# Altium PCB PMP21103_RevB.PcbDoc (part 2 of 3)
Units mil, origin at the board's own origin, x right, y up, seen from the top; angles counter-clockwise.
Board outline 3500 x 4000 mil, 4 copper layers (Top Layer, Signal Layer 1, Signal Layer 2, Bottom Layer), stack 61.2 mil thick; 194 components, 123 nets, 630 pads, 189 vias.
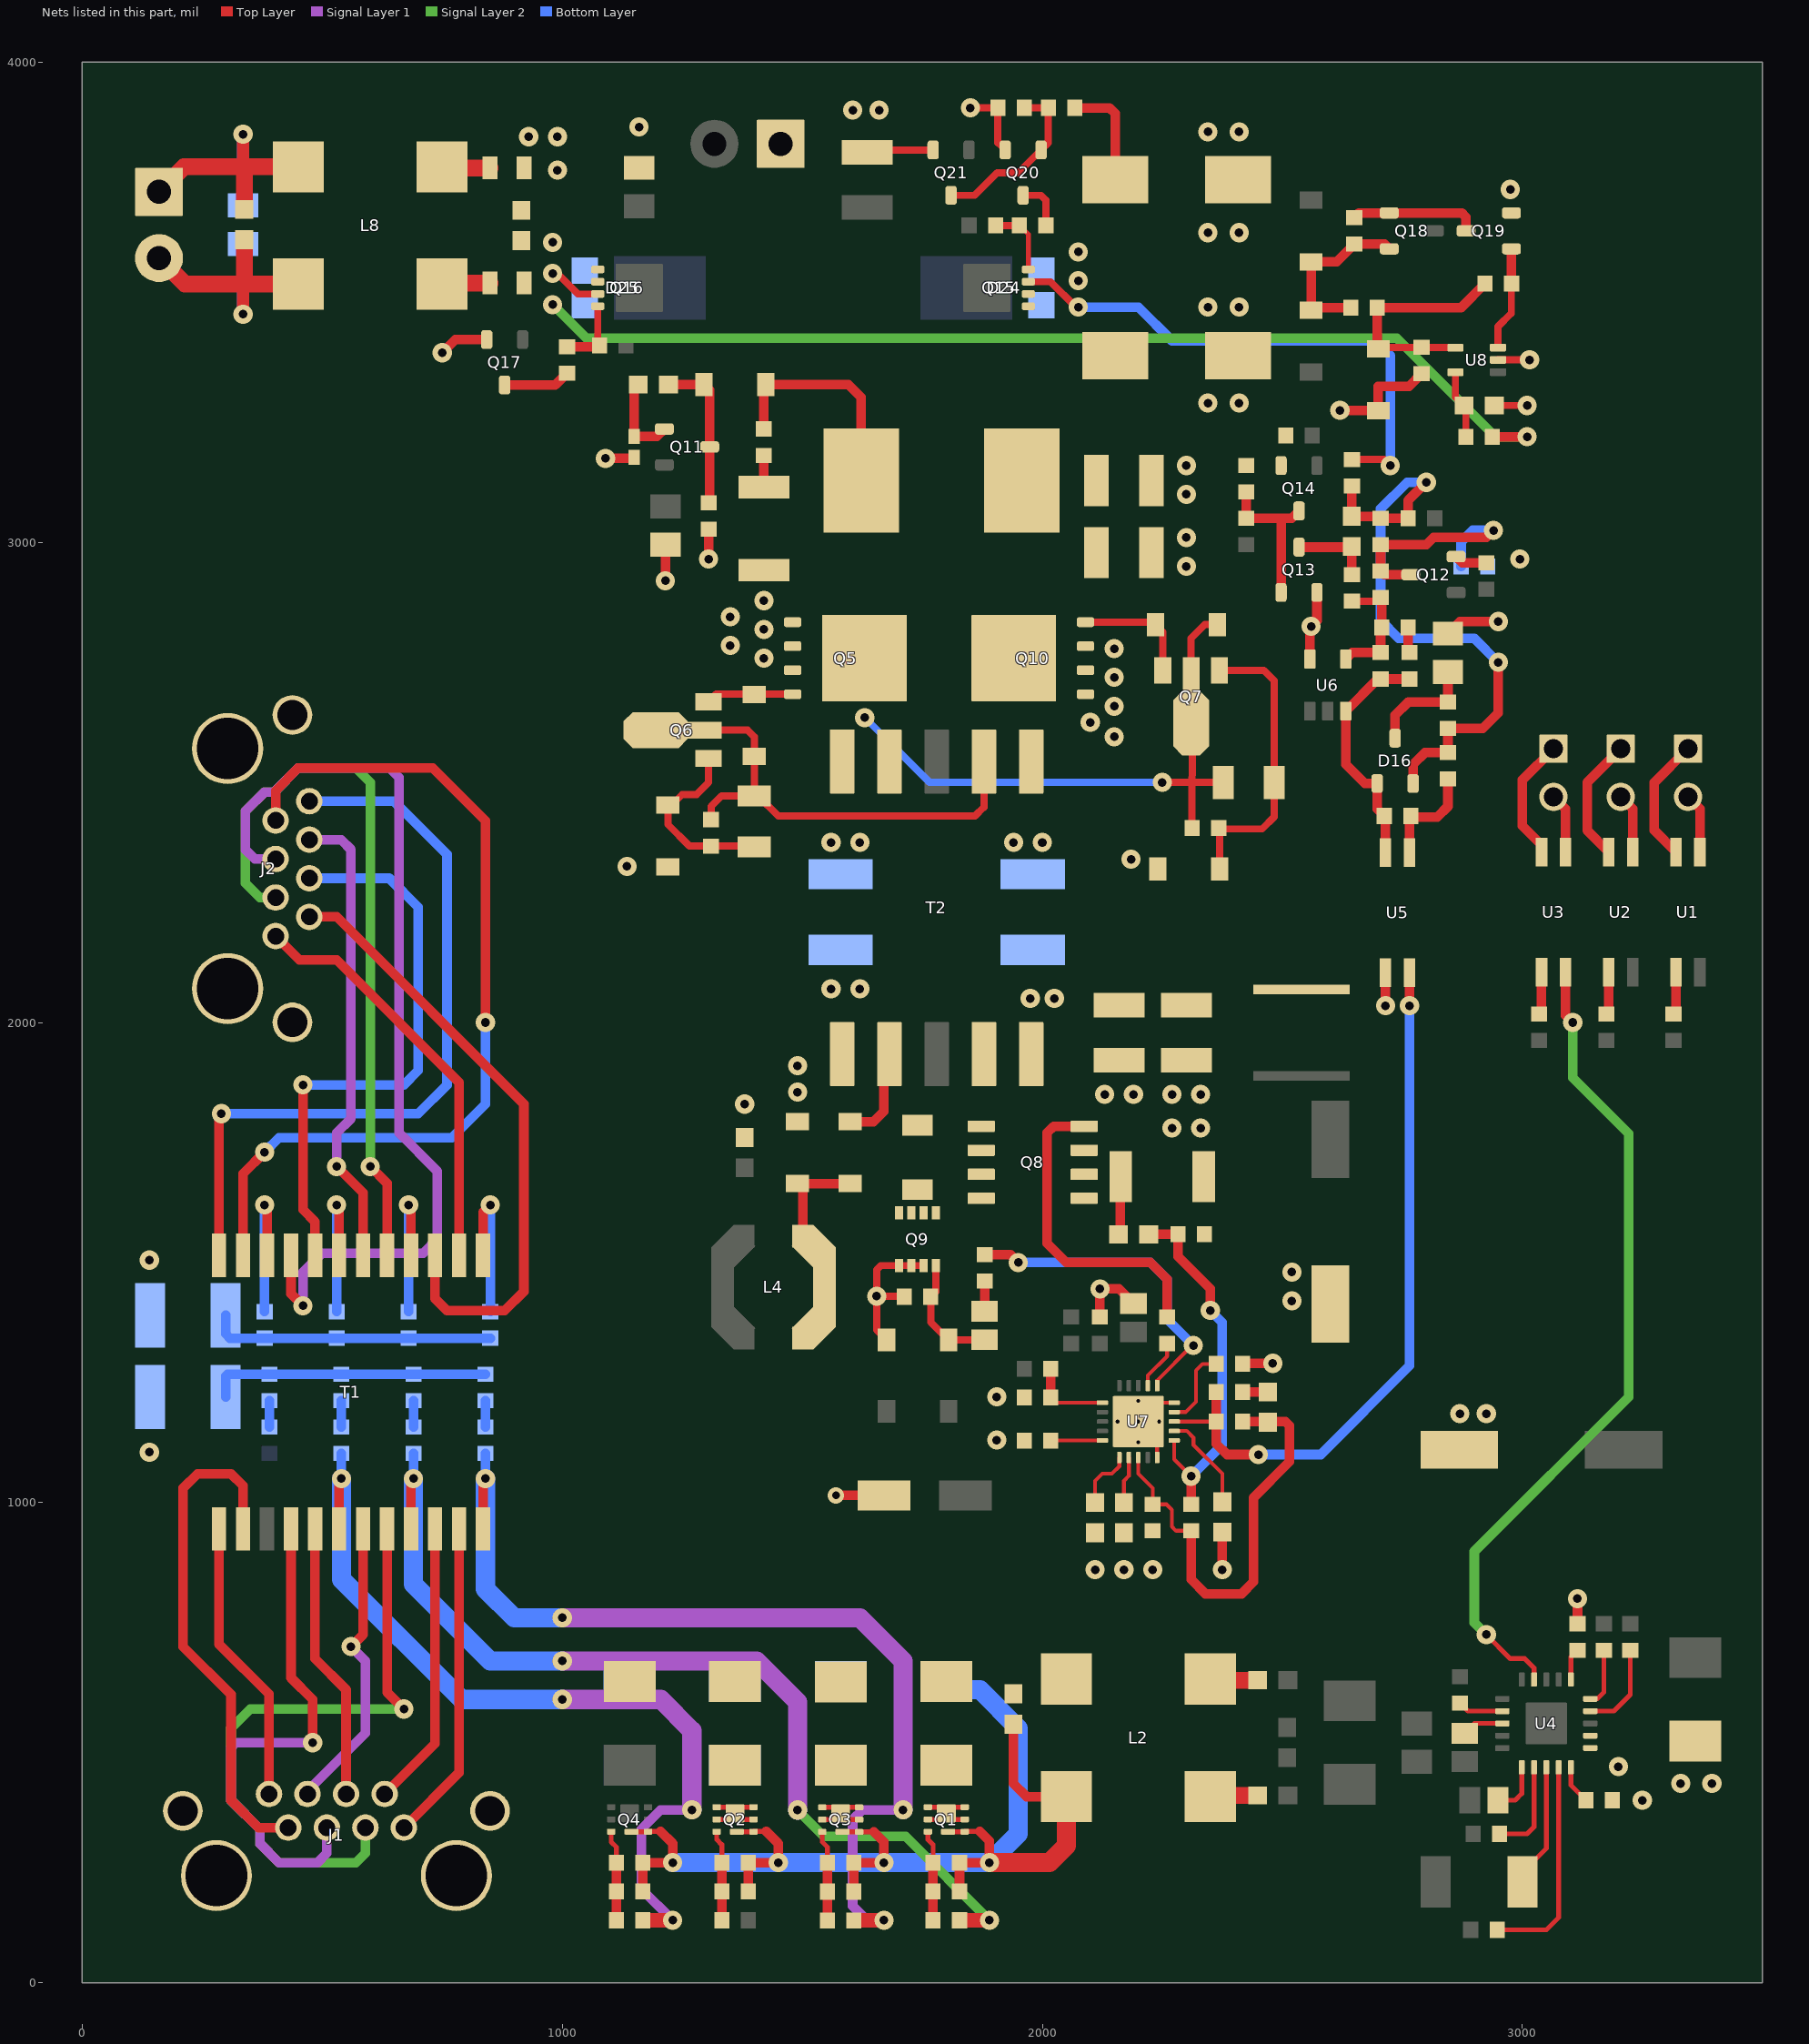
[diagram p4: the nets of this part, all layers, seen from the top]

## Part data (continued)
D10 D12: "Diode, Zener, 10 V, 500 mW, SOD-123", Manufacturer="Diodes Inc.", Power_W=0.5, Supplier Part Number 1=MMSZ5240B-FDICT-ND, Value1=0.5W
D15: "Diode, Zener, 9.1 V, 300 mW, SOD-523", Manufacturer="Diodes Inc.", Power_W=0.3, Supplier Part Number 1=BZT52C9V1TDICT-ND, Value1=0.3W
D16: "Diode, Schottky, 30 V, 0.2 A, SOT-23", Manufacturer="Diodes Inc.", Supplier Part Number 1=BAT54S-FDICT-ND, Value1=0.2A, Value2=0.65V
D18: "Diode, Zener, 5.1 V, 500 mW, SOD-123", Manufacturer="Diodes Inc.", Power_W=0.5, Supplier Part Number 1=MMSZ5231B-FDICT-ND, Value1=0.5W
D20 D21 D22 D23: library part CMP-0028397-2, "Diode, Schottky, 100 V, 2 A, SMB", Manufacturer="Diodes Inc.", Value1=2A, Value2=0.79V
D24 D25: library part CMP-0076913-1, "Diode, Schottky, 35 V, 8 A, PowerDI5", Manufacturer="Diodes Inc.", Supplier Part Number 1=PDS835LDICT-ND, Value1=8A, Value2=0.46V
D26: library part CMP-0029032-2, "Diode, Switching, 100 V, 0.2 A, SOD-123", Manufacturer="ON Semiconductor", Value1=0.2A, Value2=1V
J1 J2: "RJ-45, Right Angle, No LED, tab up", Manufacturer=AMP, Supplier Part Number 1=A97716-ND
J3 J4 J5: "Header, 100mil, 2x1, Tin, TH", Manufacturer="Sullins Connector Solutions", Supplier Part Number 1=S1012E-02-ND
J6 J7: library part CMP-0074913-1, "Terminal Block, 3.5mm Pitch, 2x1, TH", Color=Grey, Current_A=6A, Manufacturer="On-Shore Technology", Supplier Part Number 1=ED1514-ND, Voltage_V=150V
L1 L3: "Ferrite Bead, 220 ohm @ 100 MHz, 2.2 A, 0603", Manufacturer=TDK, Supplier Part Number 1=445-1565-1-ND, Value1="0.05 ohm", Value2=2.2A
L2: "Coupled inductor, 250 µH,  A, 0.035 ohm, SMD", Manufacturer="Wurth Elektronik", Supplier Part Number 1=732-1491-1-ND, ValueDisplayed=250µH
L4: "Inductor, Shielded Drum Core, Ferrite, 1.5 mH, 0.14 A, 4.6 ohm, SMD", Manufacturer=Coilcraft, Value1="4.6 ohm", Value2=0.14A, ValueDisplayed=1.5mH
L5: "Inductor, Shielded Drum Core, Ferrite, 3.3 µH, 1.73 A, 0.03 ohm, SMD", Manufacturer=Coilcraft, Value1="0.03 ohm", Value2=1.73A, ValueDisplayed=3.3µH
L6: "Inductor, Shielded Drum Core, Ferrite, 22 µH, 4 A, 0.04 ohm, SMD", Manufacturer=Coilcraft, Value1="0.04 ohm", Value2=4A, ValueDisplayed=22µH
L7 L9: library part CMP-0003428-2, "Ferrite Bead, 30 ohm @ 100 MHz, 6 A, 0805", Manufacturer=TDK, Supplier Part Number 1=445-1566-1-ND, Value1="0.01 ohm", Value2=6A, ValueDisplayed="30 ohm"
L8: library part CMP-0078807-1, "Coupled inductor, 9 µH, 0.011 ohm, SMD", Manufacturer="Wurth Elektronik", Supplier Part Number 1=732-2215-1-ND, ValueDisplayed=9µH
Q1 Q2 Q3 Q4: "MOSFET, N-CH, 100 V, 4.5 A, DQK0006C (WSON-6)", Alternate Manufacturer=None, Manufacturer="Texas Instruments", Value1="? ohm", Value2="? nC"
Q5 Q10: "MOSFET, N-CH, 60 V, 50 A, DQJ0008A (VSONP-8)", Alternate Manufacturer=None, Manufacturer="Texas Instruments", Supplier Part Number 1=296-35583-1-ND, Value1="0.0098 ohm", Value2="22 nC"
Q6 Q7: library part "FCX493TA, Diodes Inc.", "Transistor, NPN, 100 V, 1 A, SOT-89", Manufacturer="Diodes Inc.", Supplier Part Number 1=FCX493CT-ND, Value1="1 A", Value2=300
Q8: "MOSFET, N-CH, 150 V, 4.1 A, SOIC-8", Alternate Manufacturer=None, Manufacturer="Fairchild Semiconductor", Supplier Part Number 1=FDS86242CT-ND, Value1="? ohm", Value2="8.9 nC"
Q9: "MOSFET, P-CH, -150 V, -3 A, QFN-8", Alternate Manufacturer=None, Manufacturer="Fairchild Semiconductor", Supplier Part Number 1=FDMC2523PCT-ND, Value1="? ohm", Value2="6.2 nC"
Q11: library part "MMBT3904-7-F, Diodes Inc.", "Transistor, NPN, 40 V, 0.2 A, SOT-23", Manufacturer="Diodes Inc.", Supplier Part Number 1=MMBT3904-FDICT-ND, Value1="0.2 A", Value2=400
Q12 Q13 Q14 Q17 Q20 Q21: "MOSFET, N-CH, 60 V, 0.36 A, SOT-23", Alternate Manufacturer=None, Manufacturer=Nexperia, Supplier Part Number 1=568-5818-1-ND, Value1="2 ohm", Value2="0.6 nC"
Q15 Q16: library part CMP-0000025-2, "MOSFET, P-CH, -20 V, -15 A, DNH0008A (VSONP-8)", Alternate Manufacturer=None, Manufacturer="Texas Instruments", Supplier Part Number 1=CSD25402Q3A-ND, Value1=0.007, Value2="7.5 nC"
Q18: "MOSFET, P-CH, -60 V, -0.3 A, SOT-23", Alternate Manufacturer=None, Manufacturer=Nexperia, Supplier Part Number 1=568-6217-1-ND, Value1="2.7 ohm", Value2="3 nC"
Q19: "MOSFET, N-CH, 100 V, 0.17 A, SOT-23", Alternate Manufacturer=None, Manufacturer="Fairchild Semiconductor", Supplier Part Number 1=BSS123NCT-ND, Value1="10 ohm", Value2="1.8 nC"
R1 R4 R6 R37 R48 R49 R55 R65: "RES, 10.0 k, 1%, 0.1 W, 0603", Manufacturer=Vishay-Dale, Power_W=0.1, Supplier Part Number 1=541-10.0KHCT-ND, TempCo="100 ppm/C", Tolerance_%=1, Value1=1%, Value2=0.1W, Value_Code=10k0, ValueDisplayed=10.0k
R2 R3 R5 R7 R8 R9 R10 R11: "RES, 75.0 ohm, 1%, 0.1W, 0603", Manufacturer=Vishay-Dale, Power_W=0.1, Supplier Part Number 1=541-75.0HCT-ND, TempCo="100 ppm/C", Tolerance_%=1, Value1=1%, Value2=0.1W, Value_Code=75R0
R12: "RES, 27.4 k, 1%, 0.1 W, 0603", Manufacturer=Vishay-Dale, Power_W=0.1, Supplier Part Number 1=541-27.4KHCT-ND, TempCo="100 ppm/C", Tolerance_%=1, Value1=1%, Value2=0.1W, Value_Code=27k4, ValueDisplayed=27.4k
R13 R14 R24 R25 R38 R42 R43 R61 R72: "RES, 0, 5%, 0.1 W, 0603", Manufacturer=Vishay-Dale, Power_W=0.1, Supplier Part Number 1=541-0.0GCT-ND, TempCo="200 ppm/C", Tolerance_%=5, Value1=5%, Value2=0.1W, Value_Code=0000, ValueDisplayed=0
R15 R16 R17 R18: "RES, 1.00 M, 1%, 0.1 W, 0603", Manufacturer=Vishay-Dale, Power_W=0.1, Supplier Part Number 1=541-1.00MHCT-ND, TempCo="100 ppm/C", Tolerance_%=1, Value1=1%, Value2=0.1W, Value_Code=1M00, ValueDisplayed=1.00M
R19: "RES, 53.6 k, 1%, 0.1 W, 0603", Manufacturer=Vishay-Dale, Power_W=0.1, Supplier Part Number 1=541-53.6KHCT-ND, TempCo="100 ppm/C", Tolerance_%=1, Value1=1%, Value2=0.1W, Value_Code=53k6, ValueDisplayed=53.6k
R20 R21 R22 R23: "RES, 232 k, 1%, 0.1 W, 0603", Manufacturer=Vishay-Dale, Power_W=0.1, Supplier Part Number 1=541-232KHCT-ND, TempCo="100 ppm/C", Tolerance_%=1, Value1=1%, Value2=0.1W, Value_Code=232k
R26: "RES, 63.4, 1%, 0.125 W, 0805", Manufacturer=Vishay-Dale, Power_W=0.125, Supplier Part Number 1=541-63.4CCT-ND, TempCo="100 ppm/C", Tolerance_%=1, Value1=1%, Value2=0.125W, Value_Code=63R4, ValueDisplayed=63.4
R27: "RES, 1.21 k, 1%, 0.125 W, 0805", Manufacturer=Vishay-Dale, Power_W=0.125, Supplier Part Number 1=541-1.21KCCT-ND, TempCo="100 ppm/C", Tolerance_%=1, Value1=1%, Value2=0.125W, Value_Code=1k21, ValueDisplayed=1.21k
R28: library part CMP-0016077-3, "RES, 1.3 k, 5%, 0.75 W, AEC-Q200 Grade 0, 2010", Manufacturer=Vishay-Dale, Power_W=750mW, Supplier Part Number 1=541-1.3KWCT-ND, TempCo="200 ppm/C", Tolerance_%=5%, Value2=0.75W, Value_Code=1k30, ValueDisplayed=1.3k
R29: "RES, 49.9 k, 1%, 0.1 W, 0603", Manufacturer=Vishay-Dale, Power_W=0.1, Supplier Part Number 1=541-49.9KHCT-ND, TempCo="100 ppm/C", Tolerance_%=1, Value1=1%, Value2=0.1W, Value_Code=49k9, ValueDisplayed=49.9k
R30 R31: "RES, 2.0 k, 5%, 0.25 W, 1206", Manufacturer=Vishay-Dale, Power_W=0.25, Supplier Part Number 1=541-2.0KECT-ND, TempCo="200 ppm/C", Tolerance_%=5, Value1=5%, Value2=0.25W, Value_Code=2k00, ValueDisplayed=2.0k
R32: "RES, 10, 5%, 0.75 W, AEC-Q200 Grade 0, 2010", Manufacturer=Vishay-Dale, Power_W=0.75, Supplier Part Number 1=541-10.0WCT-ND, TempCo="200 ppm/C", Tolerance_%=5, Value1=5%, Value2=0.75W, Value_Code=10R0, ValueDisplayed=10
R33 R41: "RES, 4.7, 5%, 0.1 W, 0603", Manufacturer=Vishay-Dale, Power_W=0.1, Supplier Part Number 1=541-4.7GCT-ND, TempCo="200 ppm/C", Tolerance_%=5, Value1=5%, Value2=0.1W, Value_Code=4R70, ValueDisplayed=4.7
R34 R35: "RES, 121 k, 1%, 0.1 W, 0603", Manufacturer=Vishay-Dale, Power_W=0.1, Supplier Part Number 1=541-121KHCT-ND, TempCo="100 ppm/C", Tolerance_%=1, Value1=1%, Value2=0.1W, Value_Code=121k
R36 R60 R73: "RES, 1.00 k, 1%, 0.1 W, 0603", Manufacturer=Vishay-Dale, Power_W=0.1, Supplier Part Number 1=541-1.00KHCT-ND, TempCo="100 ppm/C", Tolerance_%=1, Value1=1%, Value2=0.1W, Value_Code=1k00, ValueDisplayed=1.00k
R39: "RES, 4.22 k, 1%, 0.1 W, 0603", Manufacturer=Vishay-Dale, Power_W=0.1, Supplier Part Number 1=541-4.22KHCT-ND, TempCo="100 ppm/C", Tolerance_%=1, Value1=1%, Value2=0.1W, Value_Code=4k22, ValueDisplayed=4.22k
R40: "RES, 0.1 ohm, 1%, 0.5W, 2010", Manufacturer=Panasonic, Power_W=0.5, TempCo="100 ppm/C", Tolerance_%=1, Value1=1%, Value2=0.5W, Value_Code=R100
R44: "RES, 15.0 k, 1%, 0.1 W, 0603", Manufacturer=Vishay-Dale, Power_W=0.1, Supplier Part Number 1=541-15.0KHCT-ND, TempCo="100 ppm/C", Tolerance_%=1, Value1=1%, Value2=0.1W, Value_Code=15k0, ValueDisplayed=15.0k
R45: "RES, 21.5 k, 1%, 0.1 W, 0603", Manufacturer=Vishay-Dale, Power_W=0.1, Supplier Part Number 1=541-21.5KHCT-ND, TempCo="100 ppm/C", Tolerance_%=1, Value1=1%, Value2=0.1W, Value_Code=21k5, ValueDisplayed=21.5k
R46: "RES, 28.7 k, 1%, 0.1 W, 0603", Manufacturer=Vishay-Dale, Power_W=0.1, Supplier Part Number 1=541-28.7KHCT-ND, TempCo="100 ppm/C", Tolerance_%=1, Value1=1%, Value2=0.1W, Value_Code=28k7, ValueDisplayed=28.7k
R47 R51 R52 R57 R63 R64 R66 R70 R71 R75 R76: "RES, 4.99 k, 1%, 0.1 W, 0603", Manufacturer=Vishay-Dale, Power_W=0.1, Supplier Part Number 1=541-4.99KHCT-ND, TempCo="100 ppm/C", Tolerance_%=1, Value1=1%, Value2=0.1W, Value_Code=4k99, ValueDisplayed=4.99k
R50: "RES, 5.90 k, 1%, 0.1 W, 0603", Manufacturer=Vishay-Dale, Power_W=0.1, Supplier Part Number 1=541-5.90KHCT-ND, TempCo="100 ppm/C", Tolerance_%=1, Value1=1%, Value2=0.1W, Value_Code=5k90, ValueDisplayed=5.90k
R53: "RES, 80.6 k, 1%, 0.1 W, 0603", Manufacturer=Vishay-Dale, Power_W=0.1, Supplier Part Number 1=541-80.6KHCT-ND, TempCo="100 ppm/C", Tolerance_%=1, Value1=1%, Value2=0.1W, Value_Code=80k6, ValueDisplayed=80.6k
R54 R62: "RES, 2.00 k, 1%, 0.1 W, 0603", Manufacturer=Vishay-Dale, Power_W=0.1, Supplier Part Number 1=541-2.00KHCT-ND, TempCo="100 ppm/C", Tolerance_%=1, Value1=1%, Value2=0.1W, Value_Code=2k00, ValueDisplayed=2.00k
R56: "RES, 64.9 k, 1%, 0.1 W, 0603", Manufacturer=Vishay-Dale, Power_W=0.1, Supplier Part Number 1=541-64.9KHCT-ND, TempCo="100 ppm/C", Tolerance_%=1, Value1=1%, Value2=0.1W, Value_Code=64k9, ValueDisplayed=64.9k
R58: library part CMP-0021990-2, "RES, 100 k, 1%, 0.1 W, 0603", Manufacturer=Vishay-Dale, Power_W=100mW, Supplier Part Number 1=541-100KHCT-ND, TempCo="100 ppm/C", Tolerance_%=1%, Value2=0.1W, Value_Code=100k
R59 R68: "RES, 100 k, 1%, 0.1 W, 0603", Manufacturer=Vishay-Dale, Power_W=0.1, Supplier Part Number 1=541-100KHCT-ND, TempCo="100 ppm/C", Tolerance_%=1, Value1=1%, Value2=0.1W, Value_Code=100k
R67: "RES, 20.0 k, 1%, 0.1 W, 0603", Manufacturer=Vishay-Dale, Power_W=0.1, Supplier Part Number 1=541-20.0KHCT-ND, TempCo="100 ppm/C", Tolerance_%=1, Value1=1%, Value2=0.1W, Value_Code=20k0, ValueDisplayed=20.0k
R69: "RES, 12.7 k, 1%, 0.1 W, 0603", Manufacturer=Vishay-Dale, Power_W=0.1, Supplier Part Number 1=541-12.7KHCT-ND, TempCo="100 ppm/C", Tolerance_%=1, Value1=1%, Value2=0.1W, Value_Code=12k7, ValueDisplayed=12.7k
R74: library part CMP-0021116-2, "RES, 2.49 k, 1%, 0.125 W, 0805", Manufacturer=Vishay-Dale, Power_W=125mW, Supplier Part Number 1=541-2.49KCCT-ND, TempCo="100 ppm/C", Tolerance_%=1%, Value2=0.125W, Value_Code=2k49, ValueDisplayed=2.49k
T1: "Transformer, 350 uH, SMT", Manufacturer="Wurth Elektronik", ValueDisplayed=350µH
T2: library part CMP-0077243-1, "Transformer, 100.5 uH, SMT", Manufacturer=Mentech, ValueDisplayed=100.5µH
U1 U2 U3 U5: "Optocoupler, 3.75 kV, 80-160% CTR, SMT", Manufacturer="Fairchild Semiconductor", Supplier Part Number 1=HMHA2801A-ND, Voltage_Isolation_Vrms=3750V
U4: "High-Power PoE PD Interface with Advanced Startup, RGW0020B (VQFN-20)", Alternate Manufacturer="Texas Instruments", Alternate PartNumber=TPS2373-4RGWT
U6: "Adjustable Precision Shunt Regulator, DBV0005A (SOT-23-5)", Alternate Manufacturer="Texas Instruments", Alternate PartNumber=TL431AIDBVT
U7: library part CMP-0031996-2, "Advanced Active Clamp PWM Controller with Current Control, -40 to +125 degC, 20-pin QFN (RGP), Green (RoHS & no Sb/Br)", Frequency(Max)(kHz)=1000, Manufacturer="Texas Instruments", Rating=Catalog
U8: library part CMP-0032337-1, "Single Voltage Detector, 1 Supply Monitored, -40 to 85 degC, 5-pin SC70 (DCK), Green (RoHS & no Sb/Br)", Manufacturer="Texas Instruments", Rating=Catalog, Threshold Voltage 1 (typ)(Typ)(V)=Adjustable

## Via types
v1: diameter 40, hole 18, Top Layer to Bottom Layer, 163 vias
v2: diameter 30, hole 12, Top Layer to Bottom Layer, 12 vias
v3: diameter 19.68, hole 7.87, Top Layer to Bottom Layer, 10 vias
v4: diameter 34, hole 16, Top Layer to Bottom Layer, 4 vias

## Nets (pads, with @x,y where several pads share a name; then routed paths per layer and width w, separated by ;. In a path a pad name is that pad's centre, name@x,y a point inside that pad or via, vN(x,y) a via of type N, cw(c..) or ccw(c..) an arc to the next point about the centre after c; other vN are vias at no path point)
12V_AUX: C43.1 D25.1 D25.2 L7.1 Q16.1 Q16.2 Q16.3 R68.1 | length 2318.1
  Top Layer w15: v1@990,3560 1032.8,3517.2 Q16.3@1073.98,3517.2
  Top Layer w20: R68.1@2937.56,3220 v1(3010,3220)
  Signal Layer 2 w20: v1(980,3495) 1050,3425 2738.74,3425 2943.74,3220 v1(3010,3220)
  other v1: 980,3560 980,3625
12V_POE: C18.1 C22.1 C23.1 C37.1 D24.1 D24.2 L6.2 Q15.1 Q15.2 Q15.3 R42.2 R75.2 | length 1354.2
  Top Layer w15: Q15.3@1971.02,3542.8 2017.2,3542.8 v1@2070,3490 ; R42.2@2645,3172.56 2712.44,3172.56 v1(2725,3160)
  Top Layer w20: R75.2@2067.56,3905 2140,3905 2152.05,3892.95 C37.1@2152.05,3755
  Bottom Layer w20: v1(2075,3490) 2200,3490 2270,3420 2693.74,3420 2725,3388.74 v1(2725,3160)
  other v1: 2075,3545 2075,3605
BSVG: C1.1 C6.2 J1.9 J1.10 J1.11 J1.12 J2.9 J2.10 J2.11 J2.12
  other v1: 140,1105 140,1505
BT: U3.2 U4.19 | length 1730.4
  Top Layer w10: v1(2925,725) 2975,675 3005,675 3024.41,655.59 U4.19@3024.41,631.54
  Top Layer w20: U3.2@3090,2105 3090,2015 v1(3105,2000)
  Signal Layer 2 w20: v1(2925,725) 2900,750 2900,898.31 3221.69,1220 3221.69,1768.31 3105,1885 v1(3105,2000)
GND: C16.1 C18.2 C22.2 C23.2 C29.1 C30.1 C31.2 C36.2 C37.2 C40.2 C41.2 C43.2 C44.1 D10.2 D12.2 D15.2 D18.2 J3.2 J4.2 J5.2 J6.1 L9.1 Q5.1 Q5.2 Q5.3 Q10.1 Q10.2 Q10.3 Q12.2 Q13.2 Q14.2 Q17.2 Q19.2 Q20.2 Q21.2 R32.1 R51.1 R52.1 R57.1 R69.1 R72.1 R76.1 U1.3 U2.3 U3.3 U6.5 U8.2 | length 1660.9
  Top Layer w15: C40.2@1640.16,3817.24 Q21.2@1772.6,3817.24 ; v1(1850,3905) R76.1@1907.44,3905 1907.44,3832.4 Q20.2@1922.6,3817.24 ; R69.1@2941.5,3285 v1(3010,3285) ; U8.2@2949.29,3380 v1(3015,3380)
  Top Layer w20: v1(750,3395) 777.24,3422.24 Q17.2@842.6,3422.24 ; v1(1090,3175) D15.2@1147.91,3175 ; v1(1215,2920) C31.2@1215,2995 ; v1(1305,2965) C30.1@1305,3027.44 ; U6.5@2557.4,2756.9 2557.4,2822.4 v1(2560,2825) 2572.21,2837.21 Q13.2@2572.21,2895.52 ; v1(2620,3275) D18.2@2699.27,3275 ; D18.2@2700,3274.27 2700,3325 2763.82,3325 C44.1@2790,3351.18 ; C36.2@2845,2810 2870,2835 v1(2950,2835) ; Q12.2@2862.05,2970.17 2874.66,2957.56 R52.1@2925,2957.56 ; Q19.2@2968.86,3686.14 Q19.2@2977.24,3686.14 ; J5.2@3065,2470 3090,2445 U3.3@3090,2355 ; J4.2@3205,2470 3230,2445 U2.3@3230,2355 ; J3.2@3345,2470 3370,2445 U1.3@3370,2355
  other v1: 1135,2325 2185,2340 1560,2375 1620,2375 1940,2375 2000,2375 2150,2595 2100,2625 2150,2658.66 2150,2718.66 1420,2758.66 2150,2778.66 1350,2785 1420,2818.66 1350,2845 1420,2878.66 2300,2950 2995,2965 2300,3010 2300,3100 2300,3160 2345,3290 2410,3290 2345,3490 2410,3490 2345,3645 2410,3645 2975,3735 990,3775 930,3845 990,3845 2345,3855 2410,3855 1160,3865 1605,3900 1660,3900
NetC1_2: C1.2 R2.1 R3.1 R5.1 R7.1 | length 593.7
  Bottom Layer w20: C1.2@298.74,1390 298.74,1351.26 307.56,1342.44 R7.1@380,1342.44 R5.1@530,1342.44 R3.1@680,1342.44 R2.1@850,1342.44
NetC2_2: C2.2 R8.2 | length 54.9
  Bottom Layer w20: C2.2@840,1157.56 R8.2@840,1212.44
NetC3_2: C3.2 R9.2 | length 54.9
  Bottom Layer w20: C3.2@690,1157.56 R9.2@690,1212.44
NetC4_2: C4.2 R10.2 | length 54.9
  Bottom Layer w20: C4.2@540,1157.56 R10.2@540,1212.44
NetC5_2: C5.2 R11.2 | length 54.9
  Bottom Layer w20: C5.2@390,1157.56 R11.2@390,1212.44
NetC6_1: C6.1 R8.1 R9.1 R10.1 R11.1 | length 586.6
  Bottom Layer w20: C6.1@298.74,1220 298.74,1263.74 302.56,1267.56 R11.1@390,1267.56 R10.1@540,1267.56 R9.1@690,1267.56 R8.1@840,1267.56
NetC7_1: C7.1 D1.1 D2.1 D3.1 D4.1 L2.2
NetC7_2: C7.2 C11.2 C12.2 C13.2 C14.2 D20.2 D21.2 D22.2 D23.2 L2.3 Q1.4 Q1.7 Q2.4 Q2.7 Q3.4 Q3.7 Q4.4 Q4.7 R20.1 R21.1 R22.1 R23.1 | length 2717.3
  Top Layer w10: Q4.7@1144.06,314.41 Q4.4@1178.7,314.41 1179.29,315 1205,315 ; Q2.7@1363.74,314.41 Q2.4@1398.39,314.41 1398.98,315 1425,315 ; Q3.7@1583.74,314.09 1649.09,314.09 ; Q1.7@1803.74,314.41 Q1.4@1838.39,314.41 1838.98,315 1870,315
  Top Layer w20: R23.1@1167.87,190 C14.2@1167.87,250 v1(1230,250) 1230,290 1205,315 ; R22.1@1387.56,190 C13.2@1387.56,250 v1(1450,250) 1450,290 1425,315 ; R21.1@1607.56,189.69 C12.2@1607.56,249.69 v1@1669.68,249.68 ; 1649.09,314.09 1669.68,293.5 v1@1669.68,250 ; R20.1@1827.56,190 C11.2@1827.56,250 v1(1890,250) 1890,295 1870,315 ; C7.2@1940,538.5 1940,415 1967.44,387.56 L2.3@2050,387.56
  Top Layer w40: v1(1890,250) 2015,250 2050,285 L2.3@2050,387.56
  Bottom Layer w40: v1(1230,250) v1(1450,250) v1(1670,250) v1(1890,250) 1950,310 1950,530 1870,610 1817.01,610 D20.2@1800,627.01
NetC11_1: C11.1 Q1.3 R15.2 R20.2 | length 188.9
  Top Layer w10: Q1.3@1761.61,314.41 1761.61,298.39 1772.44,287.56 C11.1@1772.44,250
  Top Layer w20: R15.2@1772.44,130 R20.2@1772.44,190 C11.1@1772.44,250
NetC12_1: C12.1 Q3.3 R16.2 R21.2 | length 188.9
  Top Layer w10: Q3.3@1541.61,314.09 1541.61,293.39 1552.44,282.56 C12.1@1552.44,249.69
  Top Layer w20: R16.2@1552.44,129.69 R21.2@1552.44,189.69 C12.1@1552.44,249.69
NetC13_1: C13.1 Q2.3 R17.2 R22.2 | length 188.9
  Top Layer w10: Q2.3@1321.61,314.41 1321.61,298.39 1332.44,287.56 C13.1@1332.44,250
  Top Layer w20: R17.2@1332.44,130 R22.2@1332.44,190 C13.1@1332.44,250
NetC14_1: C14.1 Q4.3 R18.2 R23.2 | length 188.9
  Top Layer w10: Q4.3@1101.93,314.41 1101.93,293.07 1112.76,282.24 C14.1@1112.76,250
  Top Layer w20: R18.2@1112.76,130 R23.2@1112.76,190 C14.1@1112.76,250
NetC16_2: C16.2 C19.1 C20.1 L5.2 T2.1
  other v1: 1975,2050 2025,2050
NetC21_1: C21.1 D10.1 Q7.1 R30.1 | length 613.9
  Top Layer w15: Q7.1@2369.06,2733.54 2461.46,2733.54 2483.15,2711.85 R30.1@2483.15,2500 2483.15,2428.15 2458.09,2403.09 2369.47,2403.09 D10.1@2369.47,2320
NetC21_2: C21.2 C24.1 D11.1 D14.2 L6.1 Q5.5 Q5.6 Q5.7 Q5.8 Q5.9@1629.57,2758.74 Q7.2 Q7.4 R30.2 T2.6 T2.7 | length 1738.7
  Top Layer w15: v1(2250,2500) R30.2@2376.85,2500 ; Q7.4@2310,2623.31 2310,2800 2338.74,2828.74 D11.1@2364.47,2828.74 ; C21.2@2311.95,2405 Q7.4@2312.44,2620.87
  Top Layer w20: C24.1@1420,3236.3 1420,3324.27 D14.2@1424.47,3328.74 1596.26,3328.74 1622.68,3302.32 L6.1@1622.68,3128.74
  Bottom Layer w15: v1(1630,2635) 1765,2500 v1(2250,2500)
NetC24_2: C24.2 R32.2 | length 65.8
  Top Layer w20: R32.2@1420,3115.35 C24.2@1420,3181.18
NetC25_1: C25.1 Q8.5 Q8.6 Q8.7 Q8.8 T2.2
NetC25_2: C25.2 Q9.5 Q9.6 Q9.7 Q9.8
NetC26_1: C26.1 D9.1 Q6.2 Q6.4 Q10.5 Q10.6 Q10.7 Q10.8 Q10.9@1940.43,2758.74 R31.1 T2.9 T2.10 | length 1059.2
  Top Layer w15: Q6.4@1194.57,2608.74 Q6.2@1296.93,2608.74 1386.26,2608.74 1400,2595 D9.1@1400,2554.27 R31.1@1400,2471.89 ; C26.1@1310,2422.56 1310,2450 1331.89,2471.89 R31.1@1400,2471.89 ; T2.9@1878.43,2543.46 1878.43,2448.43 1860,2430 1450,2430 1408.11,2471.89 R31.1@1400,2471.89
NetC26_2: C26.2 D12.1 Q6.1 R31.2 | length 406.6
  Top Layer w15: Q6.1@1289.68,2549.68 Q6.1@1304.8,2549.68 1304.8,2499.8 1280,2475 1250,2475 1228.21,2453.21 D12.1@1220,2453.21 1220,2412.5 1265.06,2367.44 C26.2@1310,2367.44 R31.2@1398.15,2367.44
NetC27_1: C27.1 D13.2 Q9.4 R37.2 | length 249.7
  Top Layer w15: Q9.4@1778.39,1493.62 1778.39,1439.57 R37.2@1767.56,1428.74 1767.56,1375.65 D13.2@1804.47,1338.74 C27.1@1879.53,1338.74
NetC27_2: C27.2 R41.2 | length 62.9
  Top Layer w20: C27.2@1880,1398.27 R41.2@1880,1461.18
NetC28_1: C28.1 R36.1 R58.1 U7.6 | length 781.5
  Top Layer w8: U7.6@2274.8,1129.37 2274.8,1090.2 v1(2310,1055)
  Top Layer w20: R36.1@2217.56,1558.74 C28.1@2282.44,1558.74 2282.44,1512.56 2350,1445 v1(2350,1400) ; R58.1@2310,996.3 v1(2310,1055)
  Bottom Layer w20: v1(2310,1055) 2374.99,1119.99 2374.99,1375.01 v1(2350,1400)
NetC30_2: C30.2 D14.1 Q11.3 R44.2 | length 326.8
  Top Layer w20: R44.2@1217.56,3328.74 D14.1@1295.53,3328.74 1307.24,3317.03 Q11.3@1307.24,3198.74 C30.2@1307.24,3084.8
NetC32_1: C32.1 U7.9 | length 167.3
  Top Layer w8: U7.9@2274.8,1188.43 2298.43,1188.43 2320,1210 2320,1275 2333.74,1288.74 C32.1@2362.44,1288.74
NetC33_1: C33.1 R48.1 R49.1 R60.1 U6.4 | length 251.2
  Top Layer w15: R48.1@2645,2877.44 2697.04,2877.44 R49.1@2704.8,2885.21
  Top Layer w20: U6.4@2632.21,2756.9 2645.63,2770.32 C33.1@2704.8,2770.32 R60.1@2704.8,2820.32 ; R60.1@2707.24,2822.77 R49.1@2707.24,2882.77
NetC33_2: C33.2 C34.2 D16.1 R73.2 U5.2 U6.3 | length 504.2
  Top Layer w20: U5.2@2715,2353.74 2715,2427.44 R73.2@2712.44,2430 2697.6,2444.84 D16.1@2697.6,2497.76 2672.24,2497.76 2632.21,2537.79 U6.3@2632.21,2648.63 2698.78,2715.21 C33.2@2704.8,2715.21 C34.2@2764.8,2715.21
NetC34_1: C34.1 R60.2 | length 50
  Top Layer w20: C34.1@2762.36,2772.77 R60.2@2762.36,2822.77
NetC35_1: C35.1 R61.1 | length 55.7
  Top Layer w20: R61.1@2417.56,1230 C35.1@2469.76,1230 ; C35.1@2467.56,1228.74 C35.1@2470,1226.3
NetC35_2: C35.2 C39.2 R58.2 R62.2 U7.3 | length 944.5
  Top Layer w8: U7.3@2200,1093.94 2200,1060 2230,1030 C39.2@2230,996.3 2258.7,996.3 2270,985 2270,950 2278.82,941.18 R58.2@2310,941.18
  Top Layer w20: R58.2@2310,941.18 2310,840 2340,810 2415,810 2440,835 2440,1010 2515,1085 2515,1160 2506.26,1168.74 R62.2@2417.56,1168.74
NetC36_1: C36.1 D16.3 R55.1 | length 231.6
  Top Layer w20: D16.3@2735,2592.24 2735,2640 2762.56,2667.56 R55.1@2845,2667.56 C36.1@2845,2730
NetC42_1: C42.1 J7.2 L8.4 R74.2 | length 612.1
  Top Layer w25: v1(335,3475) 335,3537.93
  Top Layer w35: J7.2@160,3592 214.05,3537.95 L8.4@450.39,3537.95 ; 337.51,3540.44 C42.1@337.51,3630.17
  Bottom Layer w25: v1(335,3475) R74.2@335,3621.67
NetC42_2: C42.2 J7.1 L8.3 R74.1 | length 614.6
  Top Layer w25: 335,3782.05 v1(335,3850)
  Top Layer w35: J7.1@160,3730 212.05,3782.05 335,3782.05 L8.3@450.39,3782.05 ; C42.2@337.51,3693.17 337.51,3779.53
  Bottom Layer w25: R74.1@335,3701.67 v1(335,3850)
NetC44_2: C44.2 D18.1 R65.1 R67.1 U8.4 | length 490.5
  Top Layer w15: D18.1@2702.38,3405.59 U8.4@2860.71,3405.59
  Top Layer w20: D18.1@2700,3403.21 2697.56,3405.65 R65.1@2697.56,3488.74 2872.44,3488.74 R67.1@2922.44,3538.74
NetD7_1: D7.1 D8.1 L4.2 | length 224
  Top Layer w20: L4.2@1501.52,1555.04 1501.52,1652.76 D8.1@1490,1664.27 D7.1@1600,1664.27
NetD7_2: D7.2 T2.4 | length 202.8
  Top Layer w20: D7.2@1600,1793.21 1648.21,1793.21 1670,1815 1670,1922.44 T2.4@1681.57,1934.02
NetD9_2: D9.2 Q5.4 Q6.3 | length 181.8
  Top Layer w15: Q6.3@1304.8,2667.8 1320.75,2683.74 Q5.4@1479.96,2683.74
NetD11_2: D11.2 Q7.3 Q10.4 | length 249.1
  Top Layer w15: Q10.4@2090.04,2833.74 2230.53,2833.74 D11.2@2235.53,2828.74 2250.94,2813.33 Q7.3@2250.94,2733.54
NetD15_1: D15.1 Q11.1 R44.1 | length 182.8
  Top Layer w20: R44.1@1162.44,3328.74 1150,3316.3 D15.1@1150,3220.39 1197.01,3220.39 Q11.1@1212.76,3236.14
NetD16_2: D16.2 R42.1 R43.1 R45.2 R46.2 R54.1 R55.2 | length 1282.7
  Top Layer w20: R42.1@2644.8,3105.21 R45.2@2644.8,3054.26 R46.2@2700.87,3054.26 ; R46.2@2704.8,3050.32 R43.1@2762.12,3050.32 ; R43.1@2762.44,3050 2762.44,3087.44 v1(2800,3125) ; D16.2@2772.4,2497.76 2772.4,2537.4 2797.56,2562.56 R54.1@2845,2562.56 R55.2@2845,2612.44 2917.44,2612.44 2950,2645 v1(2950,2750)
  Bottom Layer w20: v1(2800,3125) 2760,3125 2704.8,3069.8 2704.8,2837.44 2742.24,2800 2900,2800 v1(2950,2750)
NetD17_1: D17.1 D19.1 Q18.2 R65.2 R66.1 | length 367.9
  Top Layer w20: R65.2@2642.44,3488.74 2565.53,3488.74 D17.1@2560,3483.21 D19.1@2560,3584.27 2613.09,3584.27 R66.1@2650,3621.18 2712.91,3621.18 Q18.2@2722.76,3611.34
NetJ1_1: J1.1 T1.23 | length 669.6
  Top Layer w20: J1.1@670.16,322.91 785,437.76 T1.23@785,944.96
NetJ1_2: J1.2 T1.22 | length 595.5
  Top Layer w20: J1.2@630,392.99 735,497.99 T1.22@735,944.96
NetJ1_3: J1.3 T1.20 | length 1328.6
  Top Layer w20: T1.20@635,944.96 635,605 v1(670,570)
  Signal Layer 2 w20: J1.3@589.84,322.91 589.84,269.84 570,250 410,250 370,290 370,320 310,380 310,530 350,570 v1(670,570)
NetJ1_4: J1.4 T1.17 | length 578.8
  Top Layer w20: T1.17@485,944.96 485,675 549.68,610.32 J1.4@549.68,392.99
NetJ1_5: J1.5 T1.16 | length 1080.2
  Top Layer w20: T1.16@435,944.96 435,635 480,590 v1(480,500)
  Signal Layer 1 w20: v1(480,500) 320,500 310,490 310,380 370,320 370,290 410,250 490,250 509.53,269.53 J1.5@509.53,322.91
NetJ1_6: J1.6 T1.19 | length 624.7
  Top Layer w20: v1(560,700) 585,725 T1.19@585,944.96
  Signal Layer 1 w20: J1.6@469.37,392.99 469.37,399.37 590,520 590,670 v1(560,700)
NetJ1_7: J1.7 T1.14 | length 1072.1
  Top Layer w20: T1.14@335,944.96 335,1035 310,1060 240,1060 210,1030 210,700 310,600 310,380 367.09,322.91 J1.7@429.21,322.91
NetJ1_8: J1.8 T1.13 | length 595.1
  Top Layer w20: T1.13@285,944.96 285,705 389.06,600.94 J1.8@389.06,392.99
NetJ2_1: J2.1 T1.2 | length 868.3
  Top Layer w20: J2.1@402.91,2179.84 452.76,2130 530,2130 785,1875 T1.2@785,1515.04
NetJ2_2: J2.2 T1.3 | length 1300.5
  Top Layer w20: J2.2@472.99,2220 530,2220 920,1830 920,1439.96 880.04,1400 760,1400 735,1425 T1.3@735,1515.04
NetJ2_3: J2.3 T1.5 | length 1534.4
  Top Layer w20: v1(600,1700) 635,1665 T1.5@635,1515.04
  Signal Layer 2 w20: J2.3@402.91,2260.16 369.84,2260.16 340,2290 340,2440 380,2480 400,2480 450,2530 570,2530 600,2500 v1(600,1700)
NetJ2_4: J2.4 T1.8 | length 1209.7
  Top Layer w20: v1(460,1870) 460,1610 485,1585 T1.8@485,1515.04
  Bottom Layer w20: v1(460,1870) 670,1870 700,1900 700,2240 639.68,2300.32 J2.4@472.99,2300.32
NetJ2_5: J2.5 T1.9 | length 2004.5
  Top Layer w20: T1.9@435,1515.04 435,1435 v1(460,1410)
  Signal Layer 1 w20: J2.5@402.91,2340.47 359.53,2340.47 340,2360 340,2440 380,2480 400,2480 450,2530 640,2530 660,2510 660,1770 740,1690 740,1549.37 710,1519.37 499.37,1519.37 460,1480 v1(460,1410)
NetJ2_6: J2.6 T1.6 | length 975.7
  Top Layer w20: v1(530,1700) 585,1645 T1.6@585,1515.04
  Signal Layer 1 w20: J2.6@472.99,2380.63 539.37,2380.63 560,2360 560,1800 530,1770 v1(530,1700)
NetJ2_7: J2.7 T1.11 | length 1889.3
  Top Layer w20: T1.11@335,1515.04 335,1685 v1(380,1730) ; J2.7@402.91,2420.79 402.91,2482.91 450,2530 730,2530 840,2420 v1(840,2000)
  Bottom Layer w20: v1(380,1730) 410,1760 770,1760 840,1830 v1(840,2000)
NetJ2_8: J2.8 T1.12 | length 1604.8
  Top Layer w20: T1.12@285,1515.04 285,1805 v1(290,1810)
  Bottom Layer w20: v1(290,1810) 700,1810 760,1870 760,2350 649.06,2460.94 J2.8@472.99,2460.94
NetJ3_1: J3.1 U1.4 | length 262.6
  Top Layer w20: U1.4@3320,2355 3275,2400 3275,2500 J3.1@3345,2570
NetJ4_1: J4.1 U2.4 | length 262.6
  Top Layer w20: U2.4@3180,2355 3135,2400 3135,2500 J4.1@3205,2570
NetJ5_1: J5.1 U3.4 | length 258.5
  Top Layer w20: U3.4@3040,2355 3040,2370 3000,2410 3000,2505 J5.1@3065,2570
NetL1_1: L1.1 L2.1 | length 96.1
  Top Layer w35: L2.1@2352.44,630 L1.1@2448.5,630
NetL2_4: L2.4 L3.1 | length 96.1
  Top Layer w35: L2.4@2352.44,390 L3.1@2448.5,390
NetL7_2: L7.2 L8.1 | length 97.9
  Top Layer w35: L8.1@751.65,3540 L7.2@849.57,3540
NetL8_2: L8.2 L9.2 | length 97.9
  Top Layer w35: L8.2@751.65,3780 L9.2@849.57,3780
NetQ8_1: Q8.1 Q8.2 Q8.3 R36.2 R40.2 | length 119.1
  Top Layer w20: R36.2@2162.44,1558.74 R40.2@2162.44,1677.8
NetQ8_4: Q8.4 R33.2 | length 672.7
  Top Layer w20: Q8.4@2087.28,1783.74 2023.74,1783.74 2010,1770 2010,1540 2050,1500 2225,1500 2260,1465 R33.2@2260,1386.3
NetQ12_3: Q12.3 R46.1 R49.2 R72.2 | length 496.6
  Top Layer w20: Q12.3@2767.56,2932.77 2712.36,2932.77 R49.2@2704.8,2940.32 R46.1@2704.8,2995.21 2800.21,2995.21 2815,3010 2925,3010 v1(2940,3025)
  Bottom Layer w20: R72.2@2872.44,2950 2872.44,3000.64 2896.81,3025 v1(2940,3025)
NetQ13_1: Q13.1 Q14.3 R47.1 R51.2 | length 323.4
  Top Layer w20: R51.2@2424.8,3105.21 R47.1@2424.8,3050.32 2519.61,3050.32 Q14.3@2534.8,3065.52 ; Q13.1@2497.4,2895.52 2497.4,3047.73
NetQ13_3: Q13.3 R45.1 R48.2 | length 174.3
  Top Layer w20: Q13.3@2534.8,2990.01 2639.61,2990.01 2644.8,2995.21 R48.2@2645,2933.05
NetQ15_4: Q15.4 R64.2 R70.2 | length 149.2
  Top Layer w10: R64.2@1952.44,3660 1971.02,3641.42 Q15.4@1971.02,3568.39
  Top Layer w15: R70.2@1902.56,3660 R64.2@1952.44,3660
NetQ16_4: Q16.4 R63.1 R71.2 | length 141.1
  Top Layer w15: Q16.4@1073.98,3491.61 1073.98,3413.46 R63.1@1077.44,3410
  Top Layer w20: R71.2@1010,3407.56 R63.1@1068.07,3407.56
NetQ17_3: Q17.3 R71.1 | length 140.2
  Top Layer w20: Q17.3@880,3327.76 985.32,3327.76 R71.1@1010,3352.44
NetQ18_1: Q18.1 Q19.3 R66.2 | length 269
  Top Layer w20: R66.2@2650,3676.3 2659.84,3686.14 Q18.1@2722.76,3686.14 2873.86,3686.14 2882.76,3677.24 Q19.3@2882.76,3648.74
NetQ19_1: Q19.1 R67.2 U8.3 | length 217.3
  Top Layer w15: U8.3@2949.29,3405.59 2949.29,3449.29 2977.24,3477.24 R67.2@2977.24,3539.06
  Top Layer w20: R67.2@2977.24,3539.06 Q19.1@2977.24,3611.34
NetQ20_1: Q20.1 Q21.3 R75.1 R76.2 | length 370.4
  Top Layer w15: Q21.3@1810,3722.76 1858.86,3722.76 1906.1,3770 1950.16,3770 Q20.1@1997.4,3817.24 2012.44,3832.28 R75.1@2012.44,3905 R76.2@1962.56,3905
NetQ20_3: Q20.3 R64.1 | length 104.3
  Top Layer w15: Q20.3@1960,3722.76 1997.24,3722.76 2007.56,3712.44 R64.1@2007.56,3660
NetR1_2: R1.2 U1.1 | length 89.5
  Top Layer w20: R1.2@3315,2017.56 3320,2022.56 U1.1@3320,2105
NetR2_2: R2.2 T1.1 | length 333.6
  Top Layer w20: T1.1@835,1515.04 835,1605 v1(850,1620)
  Bottom Layer w20: R2.2@850,1397.56 v1(850,1620)
NetR3_2: R3.2 T1.4 | length 329.5
  Top Layer w20: v1(680,1620) 685,1615 T1.4@685,1515.04
  Bottom Layer w20: R3.2@680,1397.56 v1(680,1620)
NetR4_2: R4.2 U2.1 | length 89.5
  Top Layer w20: R4.2@3175,2017.56 3180,2022.56 U2.1@3180,2105
NetR5_2: R5.2 T1.7 | length 329.5
  Top Layer w20: v1(530,1620) 535,1615 T1.7@535,1515.04
  Bottom Layer w20: R5.2@530,1397.56 v1(530,1620)
NetR6_2: R6.2 U3.1 | length 89.5
  Top Layer w20: R6.2@3035,2017.56 3040,2022.56 U3.1@3040,2105
NetR7_2: R7.2 T1.10 | length 329.5
  Top Layer w20: v1(380,1620) 385,1615 T1.10@385,1515.04
  Bottom Layer w20: R7.2@380,1397.56 v1(380,1620)
NetR12_1: R12.1 U4.2 | length 95.4
  Top Layer w10: R12.1@2870,582.44 2886.85,565.59 U4.2@2958.46,565.59
NetR13_1: R13.1 U4.14 | length 190.2
  Top Layer w10: U4.14@3141.54,565.59 3190.59,565.59 3225,600 R13.1@3225,692.44
NetR14_1: R14.1 U4.15 | length 121.6
  Top Layer w10: U4.15@3141.54,591.18 3156.18,591.18 3170,605 R14.1@3170,692.44
NetR19_1: R19.1 U4.9 | length 451.5
  Top Layer w10: R19.1@2947.56,110 3050,110 3075.59,135.59 U4.9@3075.59,448.46
NetR24_2: R24.2 U4.10 | length 81.4
  Top Layer w10: U4.10@3101.18,448.46 3101.18,411.26 R24.2@3132.44,380
NetR25_1: R25.1 U4.16 | length 66.6
  Top Layer w10: U4.16@3101.18,631.54 3101.18,678.62 R25.1@3115,692.44
NetR26_2: R26.2 U4.3 | length 86.9
  Top Layer w10: R26.2@2880,519.53 2900.47,540 U4.3@2958.46,540
NetR27_2: R27.2 U4.6 | length 109.7
  Top Layer w10: R27.2@2949.53,380 2985,380 2998.82,393.82 U4.6@2998.82,448.46
NetR28_2: R28.2 U4.8 | length 258.9
  Top Layer w10: R28.2@3000.55,210 3000.55,230.55 3050,280 U4.8@3050,448.46
NetR29_2: R29.2 U4.7 | length 201.9
  Top Layer w10: R29.2@2952.56,310 3010,310 3024.41,324.41 U4.7@3024.41,448.46
NetR33_1: R33.1 U7.12 | length 104.3
  Top Layer w8: U7.12@2219.68,1243.54 2219.68,1264.68 2260,1305 R33.1@2260,1331.18
NetR34_1: R34.1 R38.2 U7.16 | length 172
  Top Layer w8: R38.2@2017.56,1218.74 2028.19,1208.11 U7.16@2125.2,1208.11
  Top Layer w20: R38.2@2017.56,1218.74 R34.1@2017.56,1278.74
NetR41_1: R41.1 U7.11 | length 678.1
  Top Layer w8: U7.11@2239.37,1243.54 2239.37,1254.37 2312.09,1327.09 v1(2314.7,1327.09)
  Top Layer w20: R41.1@1880,1516.3 1933.7,1516.3 v1(1950,1500)
  Bottom Layer w20: v1(1950,1500) 2225,1500 2260,1465 2260,1381.79 v1(2314.7,1327.09)
NetR50_2: R50.2 U7.20 | length 107
  Top Layer w8: R50.2@2018.19,1129.37 U7.20@2125.2,1129.37
NetR53_1: R53.1 U7.1 | length 130.3
  Top Layer w8: R53.1@2110,996.3 2110,1045 2125,1060 2145,1060 2160.63,1075.63 U7.1@2160.63,1093.94
NetR54_2: R54.2 R73.1 U5.1 | length 220.5
  Top Layer w20: U5.1@2765,2353.74 2765,2427.44 2822.44,2427.44 2845,2450 R54.2@2845,2507.44
NetR56_1: R56.1 U7.2 | length 101.9
  Top Layer w8: R56.1@2170,996.3 2170,1045 2180.31,1055.31 U7.2@2180.31,1093.94
NetR59_1: R59.1 U7.7 | length 208.3
  Top Layer w8: U7.7@2274.8,1149.06 2300.94,1149.06 2315,1135 2315,1120 2375,1060 R59.1@2375,997.56
NetR61_2: R61.2 R62.1 U5.4 U7.8 | length 1502.4
  Top Layer w8: U7.8@2274.8,1168.74 R62.1@2362.44,1168.74
  Top Layer w20: R61.2@2362.44,1230 R62.1@2362.44,1168.74 2362.44,1122.56 2385,1100 v1(2450,1100) ; v1(2765,2035) U5.4@2765,2103.74
  Bottom Layer w20: v1(2450,1100) 2580,1100 2765,1285 v1(2765,2035)
NetR68_2: R68.2 R69.2 U8.5 | length 143.4
  Top Layer w15: U8.5@2860.71,3354.41 2860.71,3302.8 R69.2@2878.5,3285 2882.44,3281.06 R68.2@2882.44,3220
PGND: C9.2 C15.1 C17.2 C19.2 C20.2 C28.2 C29.2 C32.2 C38.2 C39.1 C45.2 D6.2 D8.2 D13.1 Q9.1 Q9.2 Q9.3 R24.1 R25.2 R37.1 R38.1 R39.1 R40.1 R50.1 R53.2 R56.2 R59.2 T2.5 U4.11 U4.12 U5.3 U7.5 U7.10 U7.21@2200,1168.74 | length 1001
  Top Layer w8: U7.5@2239.37,1093.94 2239.37,1129.37 v3(2200,1168.74) 2239.37,1208.11 U7.10@2274.8,1208.11
  Top Layer w15: D13.1@1675.53,1338.74 1655,1359.27 v1(1655,1430) ; R37.1@1711.18,1430 v1(1655,1430) ; Q9.3@1752.8,1493.62 Q9.2@1727.2,1493.62 Q9.1@1701.61,1493.62 1663.62,1493.62 1655,1485 v1(1655,1430)
  Top Layer w20: v4(1570,1015) C45.2@1670.35,1015 ; R39.1@2120,1386.3 v1(2120,1445) 2159.53,1445 C38.2@2190,1414.53 ; v1(2375,860) R59.2@2375,942.44 ; C32.2@2418.82,1290 v1(2480,1290) ; v1(2715,2035) U5.3@2715,2103.74 ; R25.2@3115,747.56 v1(3115,800)
  other v1: 3250,380 3330,415 3395,415 3200,450 2110,860 2170,860 2230,860 1905,1130 2870,1185 2925,1185 1905,1220 2520,1420 2520,1480 2270,1780 2330,1780 1380,1830 2130,1850 2190,1850 2270,1850 2330,1850 1490,1855 1490,1910 1560,2070 1620,2070
  other v3: 2200,1125.43 2156.69,1168.74 2243.31,1168.74 2200,1212.05
PR12: C2.1 D1.2 D20.1 Q1.1 Q1.2 Q1.5 Q1.6 Q1.8 R16.1 T1.24 | length 2239.3
  Top Layer w10: Q1.2@1761.61,340 1787.2,340 Q1.8@1800,352.8 ; Q1.1@1761.61,365.59 1787.2,365.59 Q1.8@1800,352.8 ; Q1.5@1838.39,340 1812.8,340 Q1.8@1800,352.8 ; Q1.6@1838.39,365.59 1812.8,365.59 Q1.8@1800,352.8
  Top Layer w20: T1.24@835,944.96 835,1045 v1(840,1050)
  Top Layer w30: R16.1@1607.56,129.69 v1@1669.69,129.69
  Signal Layer 1 w20: v1(1670,130) 1635,130 1605,160 1605,340 1625,360 v1(1710,360)
  Signal Layer 1 w40: v1(1000,760) 1620,760 1710,670 v1(1710,360)
  Bottom Layer w20: v1(840,1050) C2.1@840,1102.44
  Bottom Layer w40: v1(840,1050) 840,820 900,760 v1(1000,760)
PR36: C3.1 D2.2 D21.1 Q3.1 Q3.2 Q3.5 Q3.6 Q3.8 R15.1 T1.21 | length 2238.7
  Top Layer w10: Q3.2@1541.61,339.69 1567.2,339.69 Q3.8@1580,352.48 ; Q3.1@1541.61,365.28 1567.2,365.28 Q3.8@1580,352.48 ; Q3.5@1618.39,339.69 1592.8,339.69 Q3.8@1580,352.48 ; Q3.6@1618.39,365.28 1592.8,365.28 Q3.8@1580,352.48
  Top Layer w20: T1.21@685,944.96 685,1045 v1(690,1050)
  Top Layer w30: R15.1@1827.56,130 v1(1890,130)
  Signal Layer 1 w40: v1(1000,670) 1405,670 1490,585 v1(1490,359.69)
  Signal Layer 2 w20: v1(1490,359.69) 1544.69,305 1715,305 v1(1890,130)
  Bottom Layer w20: v1(690,1050) C3.1@690,1102.44
  Bottom Layer w40: v1(690,1050) 690,830 850,670 v1(1000,670)
PR45: C4.1 D3.2 D22.1 Q2.1 Q2.2 Q2.5 Q2.6 Q2.8 R18.1 T1.18 | length 1934.2
  Top Layer w10: Q2.2@1321.61,340 Q2.8@1347.2,340 ; Q2.1@1321.61,365.59 1347.2,365.59 Q2.8@1360,352.8 1372.8,365.59 Q2.6@1398.39,365.59 ; Q2.8@1372.8,340 Q2.5@1398.39,340
  Top Layer w20: T1.18@535,944.96 535,1045 v1(540,1050)
  Top Layer w30: R18.1@1167.87,130 v1(1230,130)
  Signal Layer 1 w20: v1(1230,130) 1165,195 1165,320 1205,360 v1(1270,360)
  Signal Layer 1 w40: v1(1000,590) 1205,590 1270,525 v1(1270,360)
  Bottom Layer w20: v1(540,1050) C4.1@540,1102.44
  Bottom Layer w40: v1(540,1050) 540,840 790,590 v1(1000,590)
